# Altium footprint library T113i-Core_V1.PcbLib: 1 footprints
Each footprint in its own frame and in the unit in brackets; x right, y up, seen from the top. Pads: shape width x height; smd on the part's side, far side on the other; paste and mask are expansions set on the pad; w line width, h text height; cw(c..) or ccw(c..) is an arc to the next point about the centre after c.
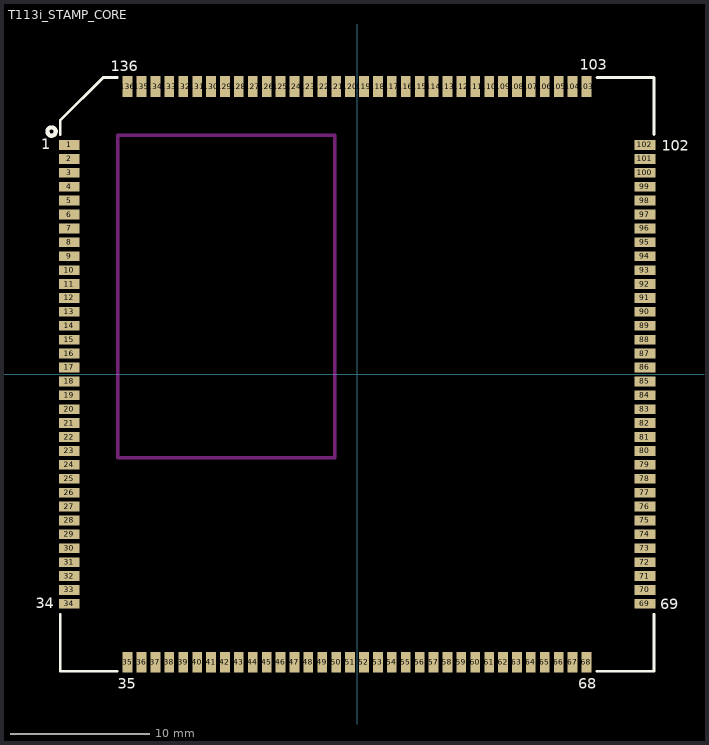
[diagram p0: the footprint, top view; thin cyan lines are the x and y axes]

## T113i_STAMP_CORE [mm]
height 1.45
pads (136):
  rect 1.5x0.7 smd: 1(-20.7,16.5) 2(-20.7,15.5) 3(-20.7,14.5) 4(-20.7,13.5) 5(-20.7,12.5) 6(-20.7,11.5) 7(-20.7,10.5) 8(-20.7,9.5) 9(-20.7,8.5) 10(-20.7,7.5) 11(-20.7,6.5) 12(-20.7,5.5) 13(-20.7,4.5) 14(-20.7,3.5) 15(-20.7,2.5) 16(-20.7,1.5) 17(-20.7,0.5) 18(-20.7,-0.5) 19(-20.7,-1.5) 20(-20.7,-2.5) 21(-20.7,-3.5) 22(-20.7,-4.5) 23(-20.7,-5.5) 24(-20.7,-6.5) 25(-20.7,-7.5) 26(-20.7,-8.5) 27(-20.7,-9.5) 28(-20.7,-10.5) 29(-20.7,-11.5) 30(-20.7,-12.5) 31(-20.7,-13.5) 32(-20.7,-14.5) 33(-20.7,-15.5) 34(-20.7,-16.5) 69(20.7,-16.5) 70(20.7,-15.5) 71(20.7,-14.5) 72(20.7,-13.5) 73(20.7,-12.5) 74(20.7,-11.5) 75(20.7,-10.5) 76(20.7,-9.5) 77(20.7,-8.5) 78(20.7,-7.5) 79(20.7,-6.5) 80(20.7,-5.5) 81(20.7,-4.5) 82(20.7,-3.5) 83(20.7,-2.5) 84(20.7,-1.5) 85(20.7,-0.5) 86(20.7,0.5) 87(20.7,1.5) 88(20.7,2.5) 89(20.7,3.5) 90(20.7,4.5) 91(20.7,5.5) 92(20.7,6.5) 93(20.7,7.5) 94(20.7,8.5) 95(20.7,9.5) 96(20.7,10.5) 97(20.7,11.5) 98(20.7,12.5) 99(20.7,13.5) 100(20.7,14.5) 101(20.7,15.5) 102(20.7,16.5)
  rect 0.7x1.5 smd: 35(-16.5,-20.7) 36(-15.5,-20.7) 37(-14.5,-20.7) 38(-13.5,-20.7) 39(-12.5,-20.7) 40(-11.5,-20.7) 41(-10.5,-20.7) 42(-9.5,-20.7) 43(-8.5,-20.7) 44(-7.5,-20.7) 45(-6.5,-20.7) 46(-5.5,-20.7) 47(-4.5,-20.7) 48(-3.5,-20.7) 49(-2.5,-20.7) 50(-1.5,-20.7) 51(-0.5,-20.7) 52(0.5,-20.7) 53(1.5,-20.7) 54(2.5,-20.7) 55(3.5,-20.7) 56(4.5,-20.7) 57(5.5,-20.7) 58(6.5,-20.7) 59(7.5,-20.7) 60(8.5,-20.7) 61(9.5,-20.7) 62(10.5,-20.7) 63(11.5,-20.7) 64(12.5,-20.7) 65(13.5,-20.7) 66(14.5,-20.7) 67(15.5,-20.7) 68(16.5,-20.7) 103(16.5,20.7) 104(15.5,20.7) 105(14.5,20.7) 106(13.5,20.7) 107(12.5,20.7) 108(11.5,20.7) 109(10.5,20.7) 110(9.5,20.7) 111(8.5,20.7) 112(7.5,20.7) 113(6.5,20.7) 114(5.5,20.7) 115(4.5,20.7) 116(3.5,20.7) 117(2.5,20.7) 118(1.5,20.7) 119(0.5,20.7) 120(-0.5,20.7) 121(-1.5,20.7) 122(-2.5,20.7) 123(-3.5,20.7) 124(-4.5,20.7) 125(-5.5,20.7) 126(-6.5,20.7) 127(-7.5,20.7) 128(-8.5,20.7) 129(-9.5,20.7) 130(-10.5,20.7) 131(-11.5,20.7) 132(-12.5,20.7) 133(-13.5,20.7) 134(-14.5,20.7) 135(-15.5,20.7) 136(-16.5,20.7)
Top Overlay:
  lines w0.2: -21.35,-17.25 -21.35,-21.35 -17.25,-21.35 ; -21.35,17.25 -21.35,18.25 -18.25,21.35 -17.25,21.35 ; 17.25,-21.35 21.35,-21.35 21.35,-17.25 ; 17.25,21.35 21.35,21.35 21.35,17.25
  lines w0.3: -21.7,17.6 ccw(c-21.968,17.466) -21.684,17.561
  text "69" at 21.8,-16.9 h0.76
  text "102" at 21.9,16.1 h0.76
  text "136" at -17.7,21.8 h0.76
  text "34" at -23.1,-16.8 h0.76
  text "68" at 15.9,-22.6 h0.76
  text "35" at -17.2,-22.6 h0.76
  text "103" at 16,21.9 h0.76
  text "1" at -22.7,16.2 h0.76
Keep-Out Layer:
  lines w0.254: -17.2,-6 -1.6,-6 -1.6,17.2 -17.2,17.2 -17.2,-6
